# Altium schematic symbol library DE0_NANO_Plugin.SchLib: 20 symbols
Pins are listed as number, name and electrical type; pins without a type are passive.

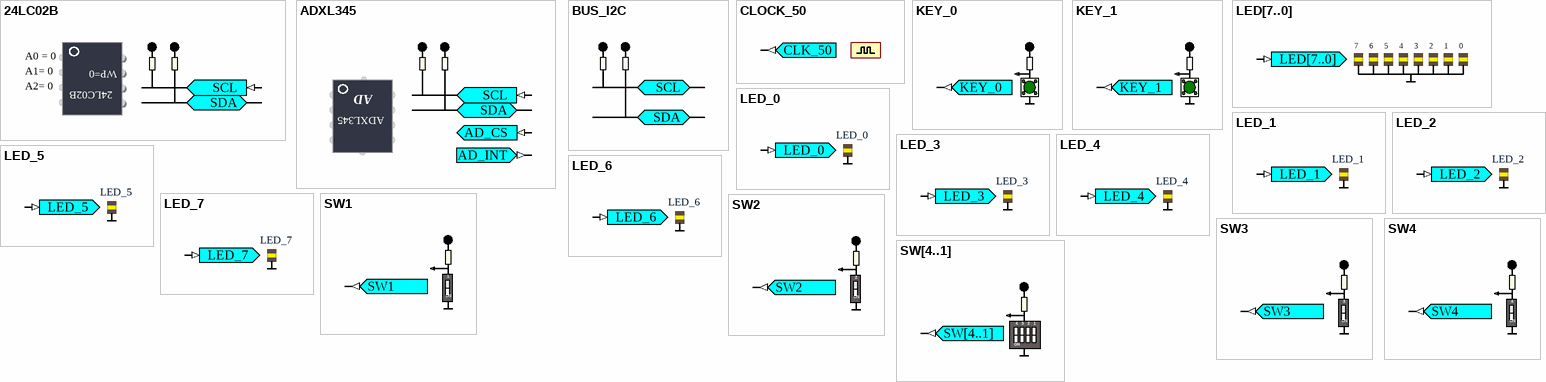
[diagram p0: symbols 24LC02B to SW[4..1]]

## 24LC02B
designator ?  (value not drawn)
Serial I2C EEPROM; PortComponent: True
pins: SCL (in), SDA (io)

## ADXL345
designator ?
Accelerometre; PortComponent: True
pins: AD_CS (in), AD_INT (out), SCL (in), SDA (io)

## BUS_I2C
designator ?
I2C Bus Interface; PortComponent: True
pins: SCL (io), SDA (io)

## CLOCK_50
designator ?
Global System Clock Supply; PortComponent: True
pins: CLK_50 (out)

## KEY_0
designator ?
Bouton poussoir (NL 1 au repos); PortComponent: True
pins: KEY_0 (out)

## KEY_1
designator ?
Bouton poussoir (NL1 au repos); PortComponent: True
pins: KEY_1 (out)

## LED[7..0]
designator ?  (value not drawn)
Bank of eight Red LEDs; PortComponent: True
pins: LED[7..0] (in)

## LED_0
designator ?
LED; PortComponent: True
pins: LED_0 (in)

## LED_1
designator ?
LED; PortComponent: True
pins: LED_1 (in)

## LED_2
designator ?
LED; PortComponent: True
pins: LED_2 (in)

## LED_3
designator ?
LED; PortComponent: True
pins: LED_3 (in)

## LED_4
designator ?
LED; PortComponent: True
pins: LED_4 (in)

## LED_5
designator ?
LED; PortComponent: True
pins: LED_5 (in)

## LED_6
designator ?
LED; PortComponent: True
pins: LED_6 (in)

## LED_7
designator ?
LED; PortComponent: True
pins: LED_7 (in)

## SW1
designator ?
Generic User Buttons; PortComponent: True
pins: SW1 (out)

## SW2
designator ?
Generic User Buttons; PortComponent: True
pins: SW2 (out)

## SW3
designator ?
Generic User Buttons; PortComponent: True
pins: SW3 (out)

## SW4
designator ?
Generic User Buttons; PortComponent: True
pins: SW4 (out)

## SW[4..1]
designator ?
Generic User Buttons; PortComponent: True
pins: SW[4..1] (out)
